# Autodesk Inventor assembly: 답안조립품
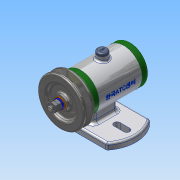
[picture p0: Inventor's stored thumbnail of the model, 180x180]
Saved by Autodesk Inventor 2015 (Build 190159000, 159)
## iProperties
Created: 2017-12
Part Number: 답안조립품
Document SubType Name: Assembly
Designer: user
Author: user
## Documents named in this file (14)
- C:\Users\user\Desktop\471207V1027\답안조립품.iam
- C:\Users\user\Desktop\471207V1027\본체.ipt
- C:\Users\user\Desktop\471207V1027\V벨트풀리.ipt
- C:\Users\user\Desktop\471207V1027\고무캡.ipt
- C:\Users\user\Desktop\471207V1027\너트 M 8.ipt
- C:\Users\user\Desktop\471207V1027\뒤커버.ipt
- C:\Users\user\Desktop\471207V1027\베어링 15 x 32 x 9.ipt
- C:\Users\user\Desktop\471207V1027\볼트 M4 x 12.ipt
- C:\Users\user\Desktop\471207V1027\스프링와셔 8.ipt
- C:\Users\user\Desktop\471207V1027\앞커버.ipt
- C:\Users\user\Desktop\471207V1027\오일 실 15 25 7.ipt
- C:\Users\user\Desktop\471207V1027\와셔 8x17.ipt
- C:\Users\user\Desktop\471207V1027\축.ipt
- C:\Users\user\Desktop\471207V1027\키 3 x 3 x 12.ipt
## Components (2 placed, 2 different names)
1. V벨트풀리:1
2. 고무캡:1
